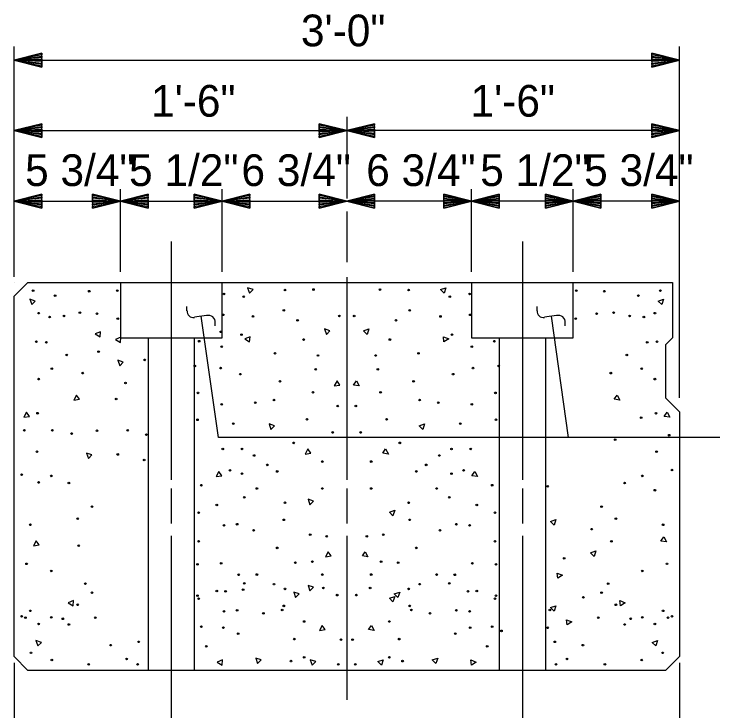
# Model space of a CAD drawing. Extents: x -408 to -23, y -15 to 117.
# Drawn here: x -91.86 to -88.678, y 30.348 to 33.49 of the extents above; entities that cross this region are included whole.
import ezdxf

# ---------------------------------------------------------------- set-up
doc = ezdxf.new("R2010")
doc.units = 0
for name, color, linetype in [('Arrowhead Terminators CELL', 7, 'Continuous'), ('Dimension Lines', 7, 'Continuous'), ('Mis Center Lines', 7, 'Continuous'), ('Sup Concrete Girder Lines', 7, 'Continuous'), ('Text', 7, 'Continuous'), ('User Information Notes', 7, 'Continuous')]:
    doc.layers.add(name, color=color, linetype=linetype)

msp = doc.modelspace()

# ---------------------------------------------------------------- linework, layer by layer
at = {"layer": 'Arrowhead Terminators CELL'}
for p, q in [((-91.0807, 32.1524), (-91.0809, 32.1708)), ((-89.5021, 32.1524), (-89.5023, 32.1708)), ((-90.9924, 32.1304), (-91.0471, 32.1227)), ((-89.4138, 32.1304), (-89.4684, 32.1227)), ((-90.9538, 32.0838), (-90.9533, 32.0975)), ((-89.3751, 32.0838), (-89.3747, 32.0975))]:
    msp.add_line(p, q, dxfattribs=at)
for centre, radius, start, end in [((-91.0531, 32.1494), 0.0276, 173.8564, 282.1419), ((-89.4745, 32.1494), 0.0276, 173.8564, 282.1419), ((-90.9846, 32.1004), 0.0311, 354.7879, 104.5868), ((-89.4059, 32.1004), 0.0311, 354.7879, 104.5868)]:
    msp.add_arc(centre, radius, start, end, dxfattribs=at)
at = {"layer": 'Dimension Lines'}
for p, q in [((-91.8602, 32.3054), (-91.8602, 33.3445)), ((-88.8602, 31.7601), (-88.8602, 33.3445)), ((-91.8602, 33.282), (-88.8602, 33.282)), ((-91.8602, 32.9646), (-90.3602, 32.9646)), ((-88.8602, 32.9646), (-90.3602, 32.9646)), ((-91.381, 32.3276), (-91.381, 32.7005)), ((-90.9227, 32.3276), (-90.9227, 32.7005)), ((-89.7977, 32.3276), (-89.7977, 32.7005)), ((-89.3393, 32.3276), (-89.3393, 32.7005)), ((-91.8602, 32.6469), (-91.381, 32.6469)), ((-91.381, 32.6469), (-90.9227, 32.6469)), ((-90.9227, 32.6469), (-90.3602, 32.6469)), ((-89.7977, 32.6469), (-90.3602, 32.6469)), ((-89.3393, 32.6469), (-89.7977, 32.6469)), ((-88.8602, 32.6469), (-89.3393, 32.6469)), ((-91.8602, 30.5642), (-91.8602, 29.9519)), ((-88.8602, 30.5642), (-88.8602, 29.9519))]:
    msp.add_line(p, q, dxfattribs=at)
for points in [[(-91.7352, 33.282), (-91.7352, 33.2758), (-91.8602, 33.282), (-91.7352, 33.2695), (-91.7352, 33.2633), (-91.8602, 33.282), (-91.7352, 33.257), (-91.7352, 33.2508), (-91.8602, 33.282), (-91.7352, 33.3133), (-91.7352, 33.307), (-91.8602, 33.282), (-91.7352, 33.3008), (-91.7352, 33.2945), (-91.8602, 33.282), (-91.7352, 33.2883), (-91.7352, 33.2508), (-91.7352, 33.3133), (-91.8602, 33.282), (-91.7352, 33.2508)], [(-88.9852, 33.282), (-88.9852, 33.2883), (-88.8602, 33.282), (-88.9852, 33.2945), (-88.9852, 33.3008), (-88.8602, 33.282), (-88.9852, 33.307), (-88.9852, 33.3133), (-88.8602, 33.282), (-88.9852, 33.2508), (-88.9852, 33.257), (-88.8602, 33.282), (-88.9852, 33.2633), (-88.9852, 33.2695), (-88.8602, 33.282), (-88.9852, 33.2758), (-88.9852, 33.3133), (-88.9852, 33.2508), (-88.8602, 33.282), (-88.9852, 33.3133)], [(-91.7352, 32.9646), (-91.7352, 32.9584), (-91.8602, 32.9646), (-91.7352, 32.9521), (-91.7352, 32.9459), (-91.8602, 32.9646), (-91.7352, 32.9396), (-91.7352, 32.9334), (-91.8602, 32.9646), (-91.7352, 32.9959), (-91.7352, 32.9896), (-91.8602, 32.9646), (-91.7352, 32.9834), (-91.7352, 32.9771), (-91.8602, 32.9646), (-91.7352, 32.9709), (-91.7352, 32.9334), (-91.7352, 32.9959), (-91.8602, 32.9646), (-91.7352, 32.9334)], [(-90.4852, 32.9646), (-90.4852, 32.9709), (-90.3602, 32.9646), (-90.4852, 32.9771), (-90.4852, 32.9834), (-90.3602, 32.9646), (-90.4852, 32.9896), (-90.4852, 32.9959), (-90.3602, 32.9646), (-90.4852, 32.9334), (-90.4852, 32.9396), (-90.3602, 32.9646), (-90.4852, 32.9459), (-90.4852, 32.9521), (-90.3602, 32.9646), (-90.4852, 32.9584), (-90.4852, 32.9959), (-90.4852, 32.9334), (-90.3602, 32.9646), (-90.4852, 32.9959)], [(-90.2352, 32.9646), (-90.2352, 32.9584), (-90.3602, 32.9646), (-90.2352, 32.9521), (-90.2352, 32.9459), (-90.3602, 32.9646), (-90.2352, 32.9396), (-90.2352, 32.9334), (-90.3602, 32.9646), (-90.2352, 32.9959), (-90.2352, 32.9896), (-90.3602, 32.9646), (-90.2352, 32.9834), (-90.2352, 32.9771), (-90.3602, 32.9646), (-90.2352, 32.9709), (-90.2352, 32.9334), (-90.2352, 32.9959), (-90.3602, 32.9646), (-90.2352, 32.9334)], [(-88.9852, 32.9646), (-88.9852, 32.9709), (-88.8602, 32.9646), (-88.9852, 32.9771), (-88.9852, 32.9834), (-88.8602, 32.9646), (-88.9852, 32.9896), (-88.9852, 32.9959), (-88.8602, 32.9646), (-88.9852, 32.9334), (-88.9852, 32.9396), (-88.8602, 32.9646), (-88.9852, 32.9459), (-88.9852, 32.9521), (-88.8602, 32.9646), (-88.9852, 32.9584), (-88.9852, 32.9959), (-88.9852, 32.9334), (-88.8602, 32.9646), (-88.9852, 32.9959)], [(-91.7352, 32.6469), (-91.7352, 32.6407), (-91.8602, 32.6469), (-91.7352, 32.6344), (-91.7352, 32.6282), (-91.8602, 32.6469), (-91.7352, 32.6219), (-91.7352, 32.6157), (-91.8602, 32.6469), (-91.7352, 32.6782), (-91.7352, 32.6719), (-91.8602, 32.6469), (-91.7352, 32.6657), (-91.7352, 32.6594), (-91.8602, 32.6469), (-91.7352, 32.6532), (-91.7352, 32.6157), (-91.7352, 32.6782), (-91.8602, 32.6469), (-91.7352, 32.6157)], [(-91.506, 32.6469), (-91.506, 32.6532), (-91.381, 32.6469), (-91.506, 32.6594), (-91.506, 32.6657), (-91.381, 32.6469), (-91.506, 32.6719), (-91.506, 32.6782), (-91.381, 32.6469), (-91.506, 32.6157), (-91.506, 32.6219), (-91.381, 32.6469), (-91.506, 32.6282), (-91.506, 32.6344), (-91.381, 32.6469), (-91.506, 32.6407), (-91.506, 32.6782), (-91.506, 32.6157), (-91.381, 32.6469), (-91.506, 32.6782)], [(-91.256, 32.6469), (-91.256, 32.6407), (-91.381, 32.6469), (-91.256, 32.6344), (-91.256, 32.6282), (-91.381, 32.6469), (-91.256, 32.6219), (-91.256, 32.6157), (-91.381, 32.6469), (-91.256, 32.6782), (-91.256, 32.6719), (-91.381, 32.6469), (-91.256, 32.6657), (-91.256, 32.6594), (-91.381, 32.6469), (-91.256, 32.6532), (-91.256, 32.6157), (-91.256, 32.6782), (-91.381, 32.6469), (-91.256, 32.6157)], [(-91.0477, 32.6469), (-91.0477, 32.6532), (-90.9227, 32.6469), (-91.0477, 32.6594), (-91.0477, 32.6657), (-90.9227, 32.6469), (-91.0477, 32.6719), (-91.0477, 32.6782), (-90.9227, 32.6469), (-91.0477, 32.6157), (-91.0477, 32.6219), (-90.9227, 32.6469), (-91.0477, 32.6282), (-91.0477, 32.6344), (-90.9227, 32.6469), (-91.0477, 32.6407), (-91.0477, 32.6782), (-91.0477, 32.6157), (-90.9227, 32.6469), (-91.0477, 32.6782)], [(-90.7977, 32.6469), (-90.7977, 32.6407), (-90.9227, 32.6469), (-90.7977, 32.6344), (-90.7977, 32.6282), (-90.9227, 32.6469), (-90.7977, 32.6219), (-90.7977, 32.6157), (-90.9227, 32.6469), (-90.7977, 32.6782), (-90.7977, 32.6719), (-90.9227, 32.6469), (-90.7977, 32.6657), (-90.7977, 32.6594), (-90.9227, 32.6469), (-90.7977, 32.6532), (-90.7977, 32.6157), (-90.7977, 32.6782), (-90.9227, 32.6469), (-90.7977, 32.6157)], [(-90.4852, 32.6469), (-90.4852, 32.6532), (-90.3602, 32.6469), (-90.4852, 32.6594), (-90.4852, 32.6657), (-90.3602, 32.6469), (-90.4852, 32.6719), (-90.4852, 32.6782), (-90.3602, 32.6469), (-90.4852, 32.6157), (-90.4852, 32.6219), (-90.3602, 32.6469), (-90.4852, 32.6282), (-90.4852, 32.6344), (-90.3602, 32.6469), (-90.4852, 32.6407), (-90.4852, 32.6782), (-90.4852, 32.6157), (-90.3602, 32.6469), (-90.4852, 32.6782)], [(-90.2352, 32.6469), (-90.2352, 32.6532), (-90.3602, 32.6469), (-90.2352, 32.6594), (-90.2352, 32.6657), (-90.3602, 32.6469), (-90.2352, 32.6719), (-90.2352, 32.6782), (-90.3602, 32.6469), (-90.2352, 32.6157), (-90.2352, 32.6219), (-90.3602, 32.6469), (-90.2352, 32.6282), (-90.2352, 32.6344), (-90.3602, 32.6469), (-90.2352, 32.6407), (-90.2352, 32.6782), (-90.2352, 32.6157), (-90.3602, 32.6469), (-90.2352, 32.6782)], [(-89.9227, 32.6469), (-89.9227, 32.6407), (-89.7977, 32.6469), (-89.9227, 32.6344), (-89.9227, 32.6282), (-89.7977, 32.6469), (-89.9227, 32.6219), (-89.9227, 32.6157), (-89.7977, 32.6469), (-89.9227, 32.6782), (-89.9227, 32.6719), (-89.7977, 32.6469), (-89.9227, 32.6657), (-89.9227, 32.6594), (-89.7977, 32.6469), (-89.9227, 32.6532), (-89.9227, 32.6157), (-89.9227, 32.6782), (-89.7977, 32.6469), (-89.9227, 32.6157)], [(-89.6727, 32.6469), (-89.6727, 32.6532), (-89.7977, 32.6469), (-89.6727, 32.6594), (-89.6727, 32.6657), (-89.7977, 32.6469), (-89.6727, 32.6719), (-89.6727, 32.6782), (-89.7977, 32.6469), (-89.6727, 32.6157), (-89.6727, 32.6219), (-89.7977, 32.6469), (-89.6727, 32.6282), (-89.6727, 32.6344), (-89.7977, 32.6469), (-89.6727, 32.6407), (-89.6727, 32.6782), (-89.6727, 32.6157), (-89.7977, 32.6469), (-89.6727, 32.6782)], [(-89.4643, 32.6469), (-89.4643, 32.6407), (-89.3393, 32.6469), (-89.4643, 32.6344), (-89.4643, 32.6282), (-89.3393, 32.6469), (-89.4643, 32.6219), (-89.4643, 32.6157), (-89.3393, 32.6469), (-89.4643, 32.6782), (-89.4643, 32.6719), (-89.3393, 32.6469), (-89.4643, 32.6657), (-89.4643, 32.6594), (-89.3393, 32.6469), (-89.4643, 32.6532), (-89.4643, 32.6157), (-89.4643, 32.6782), (-89.3393, 32.6469), (-89.4643, 32.6157)], [(-89.2143, 32.6469), (-89.2143, 32.6532), (-89.3393, 32.6469), (-89.2143, 32.6594), (-89.2143, 32.6657), (-89.3393, 32.6469), (-89.2143, 32.6719), (-89.2143, 32.6782), (-89.3393, 32.6469), (-89.2143, 32.6157), (-89.2143, 32.6219), (-89.3393, 32.6469), (-89.2143, 32.6282), (-89.2143, 32.6344), (-89.3393, 32.6469), (-89.2143, 32.6407), (-89.2143, 32.6782), (-89.2143, 32.6157), (-89.3393, 32.6469), (-89.2143, 32.6782)], [(-88.9852, 32.6469), (-88.9852, 32.6407), (-88.8602, 32.6469), (-88.9852, 32.6344), (-88.9852, 32.6282), (-88.8602, 32.6469), (-88.9852, 32.6219), (-88.9852, 32.6157), (-88.8602, 32.6469), (-88.9852, 32.6782), (-88.9852, 32.6719), (-88.8602, 32.6469), (-88.9852, 32.6657), (-88.9852, 32.6594), (-88.8602, 32.6469), (-88.9852, 32.6532), (-88.9852, 32.6157), (-88.9852, 32.6782), (-88.8602, 32.6469), (-88.9852, 32.6157)], [(-88.6777, 31.5803), (-90.9389, 31.5803), (-91.0161, 32.1277)], [(-89.3603, 31.5803), (-89.4374, 32.1277)]]:
    msp.add_lwpolyline(points, dxfattribs=at)
at = {"layer": 'Mis Center Lines'}
for p, q in [((-90.3602, 33.0276), (-90.3602, 32.6585)), ((-90.3602, 32.6002), (-90.3602, 32.3713)), ((-91.1518, 32.4646), (-91.1518, 31.3902)), ((-89.5685, 32.4646), (-89.5685, 31.3902)), ((-90.3602, 32.3032), (-90.3602, 31.4389)), ((-90.3602, 32.3032), (-90.3602, 31.3902)), ((-91.1518, 31.3513), (-91.1518, 31.1922)), ((-90.3602, 31.3513), (-90.3602, 31.1922)), ((-89.5685, 31.3513), (-89.5685, 31.1922)), ((-91.1518, 31.1371), (-91.1518, 29.6066)), ((-90.3602, 31.1371), (-90.3602, 30.3981)), ((-89.5685, 31.1371), (-89.5685, 29.6066))]:
    msp.add_line(p, q, dxfattribs=at)
at = {"layer": 'Sup Concrete Girder Lines'}
for p, q in [((-91.2561, 32.0303), (-91.2561, 30.5303)), ((-91.0476, 32.0303), (-91.0476, 30.5303)), ((-89.6727, 32.0303), (-89.6727, 30.5303)), ((-89.4643, 32.0303), (-89.4643, 30.5303))]:
    msp.add_line(p, q, dxfattribs=at)
for points in [[(-88.9227, 30.5303), (-91.7977, 30.5303), (-91.8602, 30.5928), (-91.8602, 32.2178), (-91.7977, 32.2803)], [(-91.7977, 32.2803), (-90.3602, 32.2803), (-88.8915, 32.2803), (-88.8915, 32.0303), (-88.9228, 31.999), (-88.9227, 31.7595), (-88.8602, 31.697), (-88.8602, 30.5928), (-88.9227, 30.5303)], [(-91.381, 32.2803), (-91.381, 32.0303), (-90.9227, 32.0303), (-90.9227, 32.2803)], [(-89.7977, 32.2803), (-89.7977, 32.0303), (-89.3393, 32.0303), (-89.3393, 32.2803)], [(-90.7992, 32.2319), (-90.7829, 32.2482), (-90.8074, 32.2564), (-90.7992, 32.2319)], [(-89.9212, 32.2319), (-89.9376, 32.2482), (-89.9131, 32.2564), (-89.9212, 32.2319)], [(-91.7809, 32.1798), (-91.7646, 32.1962), (-91.789, 32.2043), (-91.7809, 32.1798)], [(-88.9396, 32.1798), (-88.9559, 32.1962), (-88.9314, 32.2043), (-88.9396, 32.1798)], [(-91.4725, 32.0344), (-91.4705, 32.0574), (-91.4945, 32.0479), (-91.4725, 32.0344)], [(-90.4522, 32.0459), (-90.4358, 32.0623), (-90.4603, 32.0704), (-90.4522, 32.0459)], [(-90.2683, 32.0459), (-90.2847, 32.0623), (-90.2602, 32.0704), (-90.2683, 32.0459)], [(-91.3808, 32.0096), (-91.3788, 32.0326), (-91.4027, 32.0231), (-91.3808, 32.0096)], [(-90.7982, 32.0121), (-90.7962, 32.0351), (-90.8202, 32.0256), (-90.7982, 32.0121)], [(-89.9223, 32.0121), (-89.9242, 32.0351), (-89.9003, 32.0256), (-89.9223, 32.0121)], [(-91.3842, 31.9046), (-91.3679, 31.921), (-91.3924, 31.9291), (-91.3842, 31.9046)], [(-90.3909, 31.8174), (-90.4041, 31.8363), (-90.4164, 31.8136), (-90.3909, 31.8174)], [(-90.3296, 31.8174), (-90.3163, 31.8363), (-90.3041, 31.8136), (-90.3296, 31.8174)], [(-91.5659, 31.7529), (-91.5791, 31.7718), (-91.5914, 31.7492), (-91.5659, 31.7529)], [(-89.1546, 31.7529), (-89.1413, 31.7718), (-89.1291, 31.7492), (-89.1546, 31.7529)], [(-91.7914, 31.676), (-91.8047, 31.695), (-91.817, 31.6723), (-91.7914, 31.676)], [(-88.929, 31.676), (-88.9158, 31.695), (-88.9035, 31.6723), (-88.929, 31.676)], [(-90.7026, 31.6171), (-90.6862, 31.6334), (-90.7107, 31.6416), (-90.7026, 31.6171)], [(-90.0179, 31.6171), (-90.0342, 31.6334), (-90.0098, 31.6416), (-90.0179, 31.6171)], [(-91.5255, 31.4857), (-91.5092, 31.502), (-91.5337, 31.5102), (-91.5255, 31.4857)], [(-90.5222, 31.51), (-90.5355, 31.5289), (-90.5477, 31.5062), (-90.5222, 31.51)], [(-90.1983, 31.51), (-90.185, 31.5289), (-90.1727, 31.5062), (-90.1983, 31.51)], [(-90.9238, 31.4083), (-90.9371, 31.4272), (-90.9493, 31.4046), (-90.9238, 31.4083)], [(-89.7966, 31.4083), (-89.7834, 31.4272), (-89.7711, 31.4046), (-89.7966, 31.4083)], [(-90.5265, 31.2775), (-90.5102, 31.2938), (-90.5347, 31.3019), (-90.5265, 31.2775)], [(-90.1518, 31.2279), (-90.1681, 31.2442), (-90.1437, 31.2524), (-90.1518, 31.2279)], [(-89.4255, 31.1857), (-89.4418, 31.2021), (-89.4174, 31.2102), (-89.4255, 31.1857)], [(-88.9439, 31.1133), (-88.9306, 31.1322), (-88.9184, 31.1096), (-88.9439, 31.1133)], [(-91.7468, 31.096), (-91.7601, 31.1149), (-91.7724, 31.0922), (-91.7468, 31.096)], [(-90.4305, 31.0464), (-90.4438, 31.0653), (-90.456, 31.0427), (-90.4305, 31.0464)], [(-90.29, 31.0464), (-90.2767, 31.0653), (-90.2645, 31.0427), (-90.29, 31.0464)], [(-89.2445, 31.0444), (-89.2609, 31.0608), (-89.2364, 31.0689), (-89.2445, 31.0444)], [(-89.4091, 30.9462), (-89.4111, 30.9692), (-89.3872, 30.9597), (-89.4091, 30.9462)], [(-90.5265, 30.8893), (-90.5102, 30.9057), (-90.5347, 30.9138), (-90.5265, 30.8893)], [(-90.591, 30.8585), (-90.5747, 30.8749), (-90.5991, 30.883), (-90.591, 30.8585)], [(-90.1295, 30.8585), (-90.1458, 30.8749), (-90.1213, 30.883), (-90.1295, 30.8585)], [(-91.5939, 30.8222), (-91.592, 30.8452), (-91.6159, 30.8357), (-91.5939, 30.8222)], [(-90.1518, 30.8397), (-90.1681, 30.8561), (-90.1437, 30.8642), (-90.1518, 30.8397)], [(-89.1265, 30.8222), (-89.1285, 30.8452), (-89.1046, 30.8357), (-89.1265, 30.8222)], [(-89.4255, 30.7976), (-89.4418, 30.814), (-89.4174, 30.8221), (-89.4255, 30.7976)], [(-89.367, 30.7355), (-89.369, 30.7584), (-89.345, 30.749), (-89.367, 30.7355)], [(-90.4578, 30.7142), (-90.4711, 30.7331), (-90.4833, 30.7105), (-90.4578, 30.7142)], [(-90.2627, 30.7142), (-90.2494, 30.7331), (-90.2372, 30.7105), (-90.2627, 30.7142)], [(-91.7536, 30.6404), (-91.7373, 30.6567), (-91.7617, 30.6649), (-91.7536, 30.6404)], [(-88.9668, 30.6404), (-88.9832, 30.6567), (-88.9587, 30.6649), (-88.9668, 30.6404)], [(-90.7621, 30.561), (-90.7457, 30.5774), (-90.7702, 30.5855), (-90.7621, 30.561)], [(-89.9584, 30.561), (-89.9748, 30.5774), (-89.9503, 30.5855), (-89.9584, 30.561)], [(-90.9222, 30.5545), (-90.9202, 30.5775), (-90.9441, 30.568), (-90.9222, 30.5545)], [(-90.5166, 30.5536), (-90.5003, 30.57), (-90.5248, 30.5781), (-90.5166, 30.5536)], [(-90.2038, 30.5536), (-90.2202, 30.57), (-90.1957, 30.5781), (-90.2038, 30.5536)], [(-89.7983, 30.5545), (-89.8003, 30.5775), (-89.7763, 30.568), (-89.7983, 30.5545)]]:
    msp.add_lwpolyline(points, dxfattribs=at)
for centre in [(-91.7744, 32.243), (-91.5216, 32.2405), (-91.3951, 32.243), (-90.639, 32.2455), (-90.5101, 32.248), (-90.2103, 32.248), (-90.0814, 32.2455), (-89.3253, 32.243), (-89.1989, 32.2405), (-88.9461, 32.243), (-91.6752, 32.2207), (-90.9142, 32.2282), (-90.825, 32.2158), (-89.8955, 32.2158), (-89.8062, 32.2282), (-89.0452, 32.2207), (-91.7496, 32.1414), (-91.5637, 32.1439), (-90.644, 32.1538), (-90.0764, 32.1538), (-89.1567, 32.1439), (-88.9709, 32.1414), (-91.7, 32.124), (-91.6356, 32.129), (-91.4868, 32.1389), (-91.3927, 32.1166), (-90.9167, 32.134), (-90.7828, 32.1265), (-90.5821, 32.1092), (-90.3936, 32.129), (-90.3268, 32.129), (-90.1384, 32.1092), (-89.9376, 32.1265), (-89.8038, 32.134), (-89.3278, 32.1166), (-89.2336, 32.1389), (-89.0849, 32.129), (-89.0204, 32.124), (-90.9291, 32.0571), (-90.8349, 32.0447), (-89.8856, 32.0447), (-91.7596, 32.0125), (-91.0258, 32.015), (-90.5548, 32.0224), (-90.1657, 32.0224), (-89.6947, 32.015), (-88.9609, 32.0125), (-91.7149, 32.01), (-90.9241, 31.9902), (-89.7963, 31.9902), (-89.0055, 32.01), (-91.6232, 31.953), (-91.4794, 31.9679), (-90.6837, 31.9604), (-90.4903, 31.9505), (-90.2301, 31.9505), (-90.0368, 31.9604), (-89.0973, 31.953), (-91.2712, 31.9307), (-91.6901, 31.891), (-91.0456, 31.9034), (-90.9291, 31.8935), (-90.5002, 31.8885), (-90.2202, 31.8885), (-89.7914, 31.8935), (-89.6749, 31.9034), (-89.0303, 31.891), (-91.551, 31.871), (-90.8399, 31.8663), (-89.8806, 31.8663), (-89.1695, 31.871), (-91.7496, 31.8439), (-91.3579, 31.8266), (-90.6614, 31.834), (-90.0591, 31.834), (-88.9709, 31.8439), (-91.0308, 31.7819), (-90.5126, 31.7844), (-90.2078, 31.7844), (-89.6897, 31.7819), (-91.4001, 31.7547), (-90.9241, 31.7299), (-90.7729, 31.7374), (-90.6886, 31.7497), (-90.0318, 31.7497), (-89.9475, 31.7374), (-89.7963, 31.7299), (-90.4011, 31.7225), (-90.3194, 31.7225), (-91.7546, 31.6902), (-90.5399, 31.663), (-90.1805, 31.663), (-89.0328, 31.6704), (-88.9659, 31.6902), (-91.0332, 31.6605), (-90.8721, 31.6431), (-89.8484, 31.6431), (-89.6873, 31.6605), (-91.8141, 31.6133), (-91.6876, 31.6133), (-91.6009, 31.5985), (-91.4868, 31.6109), (-91.348, 31.6134), (-90.4234, 31.6035), (-90.2971, 31.6035), (-91.2638, 31.5935), (-89.1499, 31.5711), (-88.9064, 31.5909), (-90.5994, 31.5564), (-90.1211, 31.5564), (-91.7571, 31.5167), (-91.3927, 31.5043), (-90.9192, 31.5291), (-90.8324, 31.5291), (-89.888, 31.5291), (-89.8013, 31.5291), (-88.9634, 31.5167), (-91.2737, 31.4795), (-90.7779, 31.4994), (-90.4705, 31.4721), (-90.25, 31.4721), (-89.9426, 31.4994), (-90.7184, 31.4572), (-90.0021, 31.4572), (-91.8265, 31.4126), (-91.6926, 31.4076), (-90.887, 31.4324), (-90.8324, 31.4176), (-90.6738, 31.4275), (-90.0467, 31.4275), (-89.888, 31.4176), (-89.8335, 31.4324), (-89.0278, 31.4076), (-88.894, 31.4339), (-91.7496, 31.3779), (-91.6133, 31.3754), (-89.1072, 31.3754), (-91.0159, 31.3655), (-90.7655, 31.3506), (-90.4705, 31.3506), (-90.25, 31.3506), (-89.955, 31.3506), (-89.7046, 31.3655), (-89.4542, 31.3605), (-88.9709, 31.343), (-90.8225, 31.3109), (-90.639, 31.2862), (-90.0814, 31.2862), (-89.898, 31.3109), (-91.5092, 31.2688), (-90.9464, 31.2763), (-89.774, 31.2763), (-89.2113, 31.2688), (-91.0283, 31.2415), (-89.6922, 31.2415), (-91.7868, 31.187), (-91.5736, 31.2142), (-90.9142, 31.1845), (-90.8547, 31.1895), (-90.644, 31.2093), (-90.0764, 31.2093), (-89.8658, 31.1895), (-89.8062, 31.1845), (-89.1468, 31.2142), (-88.9337, 31.187), (-90.7803, 31.1622), (-89.9401, 31.1622), (-89.256, 31.1672), (-90.525, 31.1424), (-90.4506, 31.135), (-90.2698, 31.135), (-90.1954, 31.1424), (-91.5687, 31.0928), (-91.0283, 31.1127), (-89.6922, 31.1127), (-89.1667, 31.1126), (-90.6738, 31.0829), (-90.0467, 31.0829), (-89.3799, 31.0358), (-91.8041, 31.011), (-91.0332, 31.0085), (-90.9266, 31.0135), (-90.592, 31.0159), (-90.5151, 31.0209), (-90.2053, 31.0209), (-90.1285, 31.0159), (-89.7938, 31.0135), (-89.6873, 31.0085), (-88.9163, 31.011), (-91.6926, 30.9788), (-90.7655, 30.9625), (-90.4705, 30.9625), (-90.25, 30.9625), (-89.955, 30.9625), (-89.0278, 30.9788), (-90.8473, 30.9614), (-89.8732, 30.9614), (-91.5389, 30.9217), (-90.8225, 30.9228), (-90.6886, 30.9193), (-90.639, 30.898), (-90.4655, 30.9019), (-90.2549, 30.9019), (-90.0814, 30.898), (-90.0318, 30.9193), (-89.898, 30.9228), (-89.1815, 30.9217), (-91.5092, 30.8807), (-91.0332, 30.8672), (-90.9464, 30.8881), (-90.9068, 30.887), (-90.8275, 30.8945), (-90.4036, 30.8697), (-90.3169, 30.8697), (-89.8137, 30.887), (-89.774, 30.8881), (-89.6873, 30.8672), (-89.2113, 30.8807), (-91.0283, 30.8534), (-89.6922, 30.8534), (-89.2931, 30.8597), (-91.5736, 30.8261), (-90.6514, 30.8028), (-90.644, 30.8212), (-90.0764, 30.8212), (-90.069, 30.8028), (-89.4443, 30.8028), (-89.1468, 30.8261), (-91.8265, 30.7744), (-91.7868, 30.7989), (-90.9142, 30.7964), (-90.8547, 30.8014), (-90.7358, 30.7879), (-89.9847, 30.7879), (-89.8658, 30.8014), (-89.8062, 30.7964), (-88.9337, 30.7989), (-88.894, 30.7744), (-91.8091, 30.768), (-91.7496, 30.7397), (-91.6926, 30.7695), (-91.6405, 30.7631), (-91.4943, 30.768), (-90.5523, 30.7507), (-90.1681, 30.7507), (-89.2262, 30.768), (-89.0799, 30.7631), (-89.0278, 30.7695), (-88.9709, 30.7397), (-88.9113, 30.768), (-91.6133, 30.7372), (-91.0159, 30.7273), (-90.9167, 30.7234), (-89.8038, 30.7234), (-89.7046, 30.7273), (-89.6625, 30.7085), (-89.4542, 30.7224), (-89.1072, 30.7372), (-90.8498, 30.6962), (-89.8707, 30.6962), (-91.4249, 30.6441), (-91.2985, 30.659), (-90.5969, 30.6714), (-90.3862, 30.6689), (-90.3342, 30.6689), (-90.1236, 30.6714), (-89.422, 30.659), (-89.2956, 30.6441), (-90.9936, 30.6391), (-89.7269, 30.6391), (-91.7843, 30.6094), (-91.353, 30.5821), (-90.5523, 30.5896), (-90.1681, 30.5896), (-89.3675, 30.5821), (-88.9361, 30.6094), (-91.6901, 30.5771), (-91.524, 30.5574), (-91.3034, 30.5574), (-90.6118, 30.5722), (-90.3986, 30.5574), (-90.3218, 30.5574), (-90.1087, 30.5722), (-89.4171, 30.5574), (-89.1964, 30.5574), (-89.0303, 30.5771)]:
    msp.add_circle(centre, 0.00364, dxfattribs=at)
at = {"layer": 'User Information Notes'}
for p, q in [((-91.8602, 32.2803), (-91.8602, 32.2803)), ((-88.8602, 32.2803), (-88.8602, 32.2803)), ((-91.8602, 30.5303), (-91.8602, 30.5303)), ((-88.8602, 30.5303), (-88.8602, 30.5303))]:
    msp.add_line(p, q, dxfattribs=at)

# ---------------------------------------------------------------- texts
at = {"layer": 'Text'}
for s, p in [('3\'-0"', (-90.5668, 33.345)), ('1\'-6"', (-91.2426, 33.0276)), ('1\'-6"', (-89.8021, 33.0276)), ('5 3/4"', (-91.8106, 32.7148)), ('5 1/2"', (-91.3419, 32.7148)), ('6 3/4"', (-90.835, 32.7148)), ('6 3/4"', (-90.2725, 32.7148)), ('5 1/2"', (-89.7585, 32.7148)), ('5 3/4"', (-89.2898, 32.7148))]:
    msp.add_text(s, height=0.14302, dxfattribs=at).set_placement(p)

doc.saveas('drawing.dxf')
